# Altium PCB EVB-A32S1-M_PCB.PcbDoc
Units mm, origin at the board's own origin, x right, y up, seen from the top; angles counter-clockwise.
Board outline 134 x 65 mm, 4 copper layers (L1 (Signal), L2 (GND), L3 (PWR), L4 (Signal)), stack 1.614 mm thick; 111 components, 86 nets, 390 pads, 0 vias.
Unrouted connection lines stored in the file: 284.
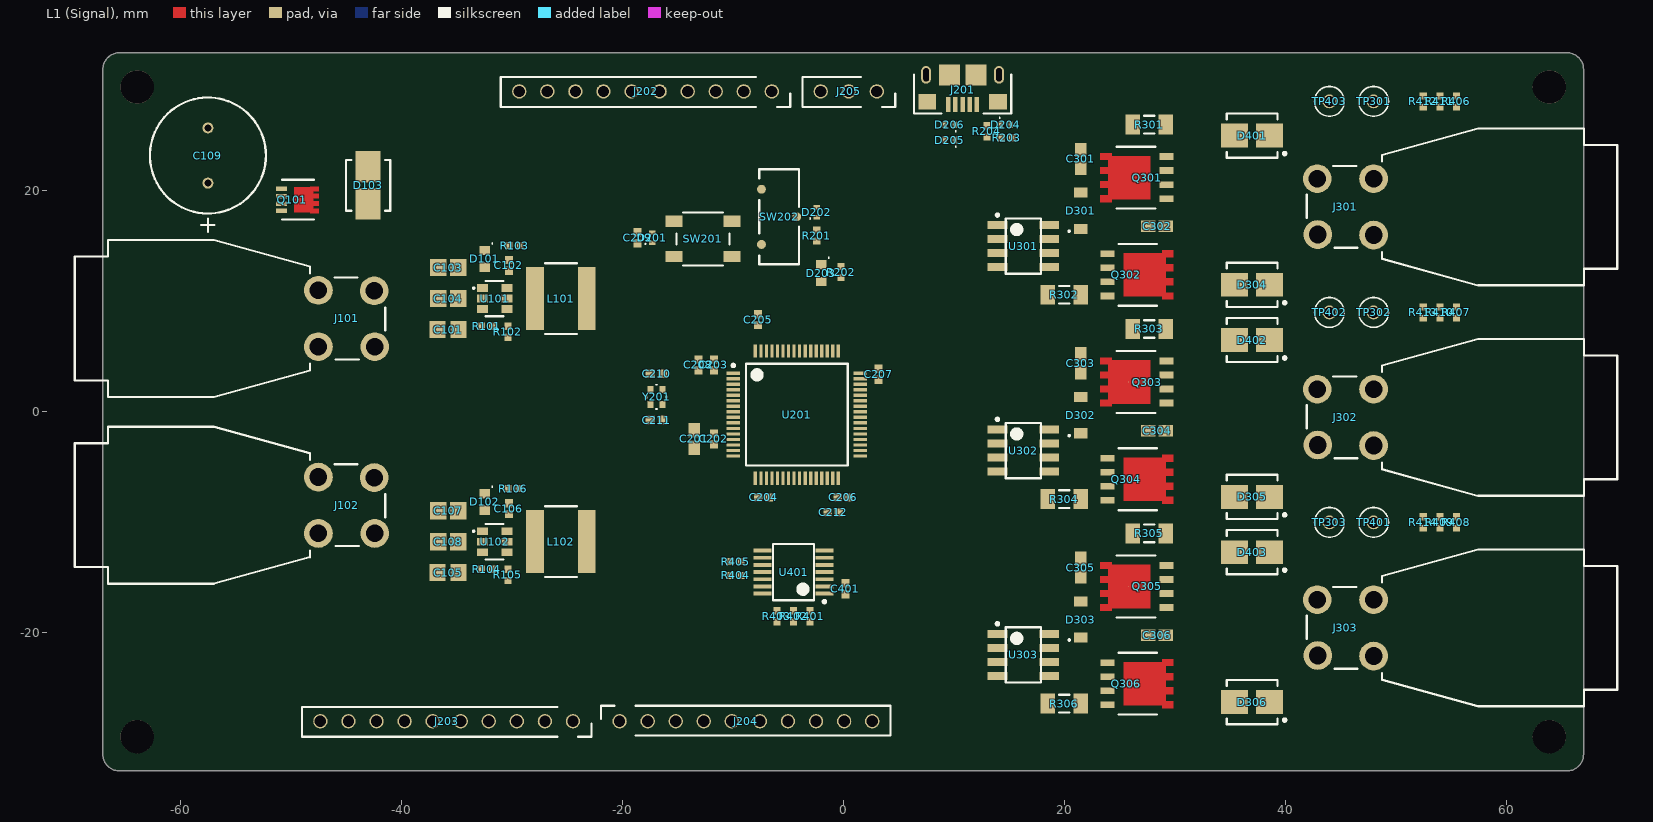
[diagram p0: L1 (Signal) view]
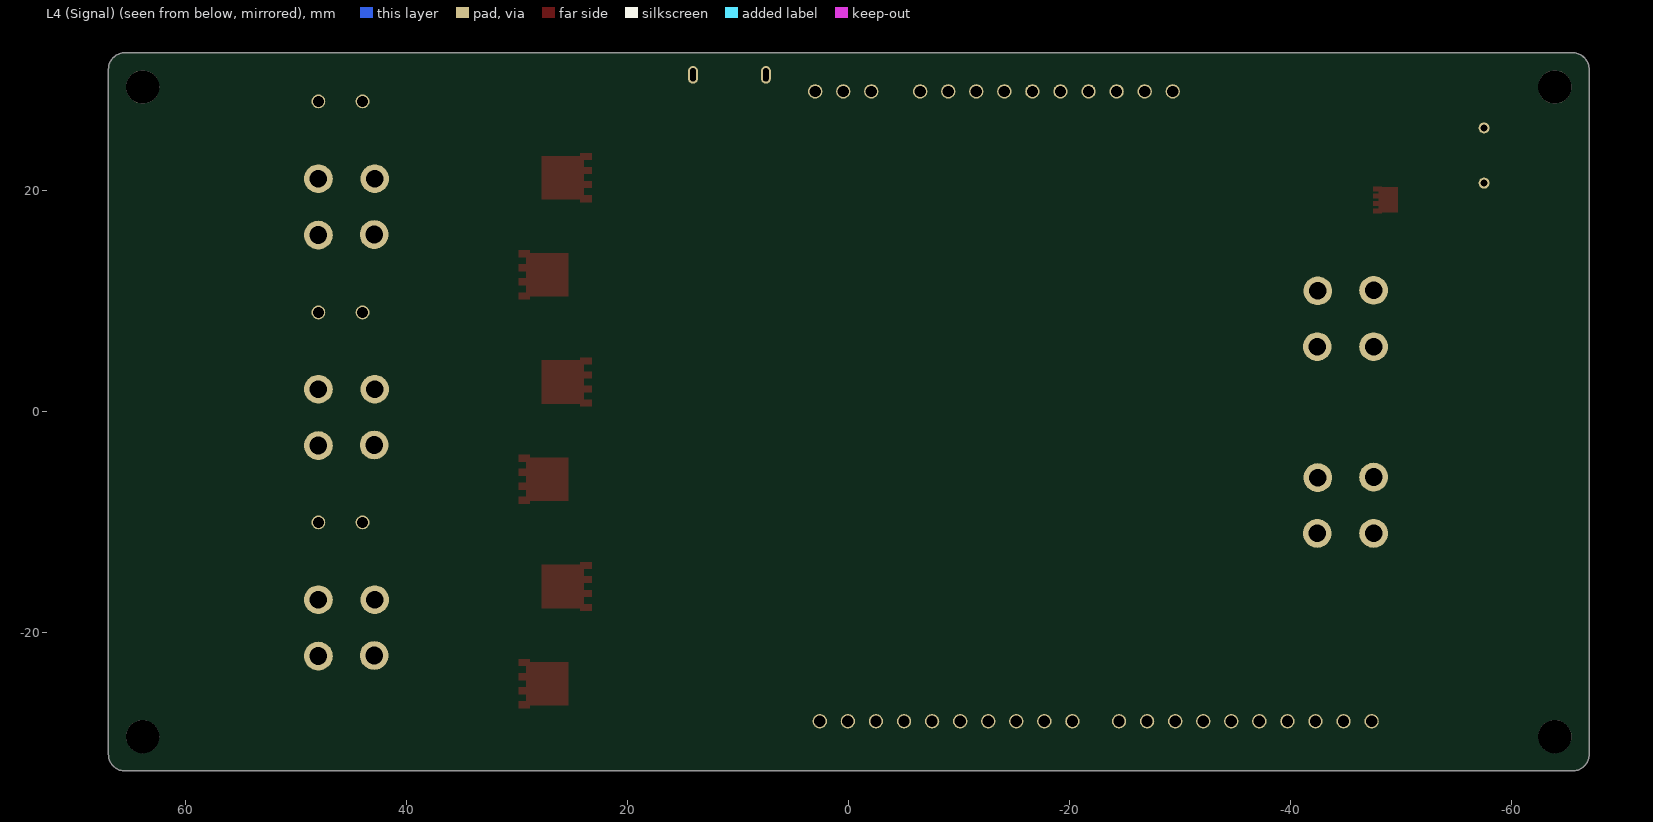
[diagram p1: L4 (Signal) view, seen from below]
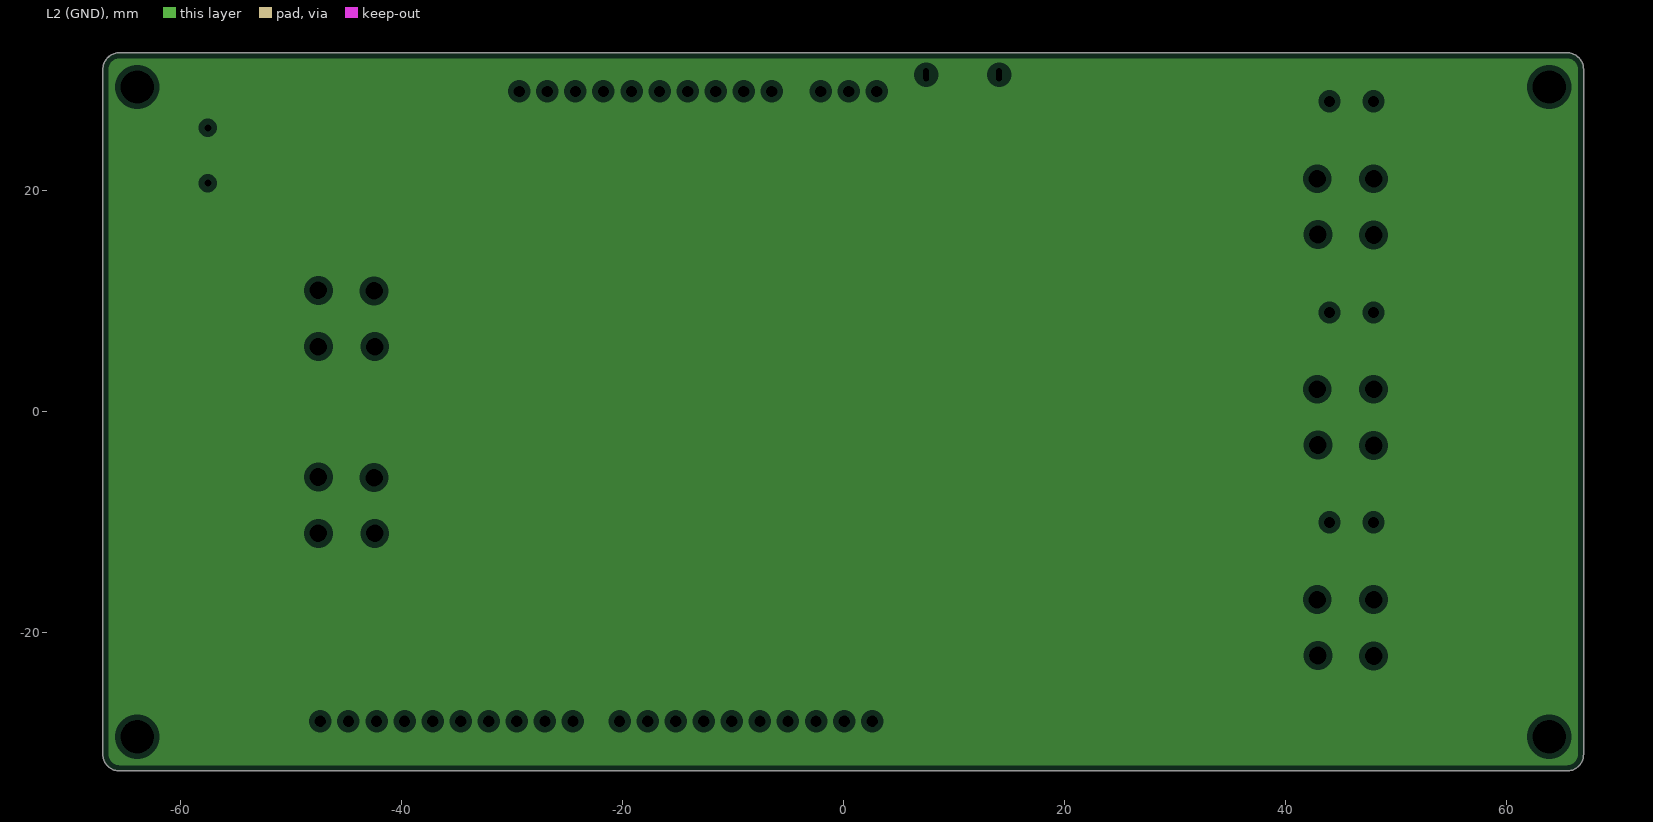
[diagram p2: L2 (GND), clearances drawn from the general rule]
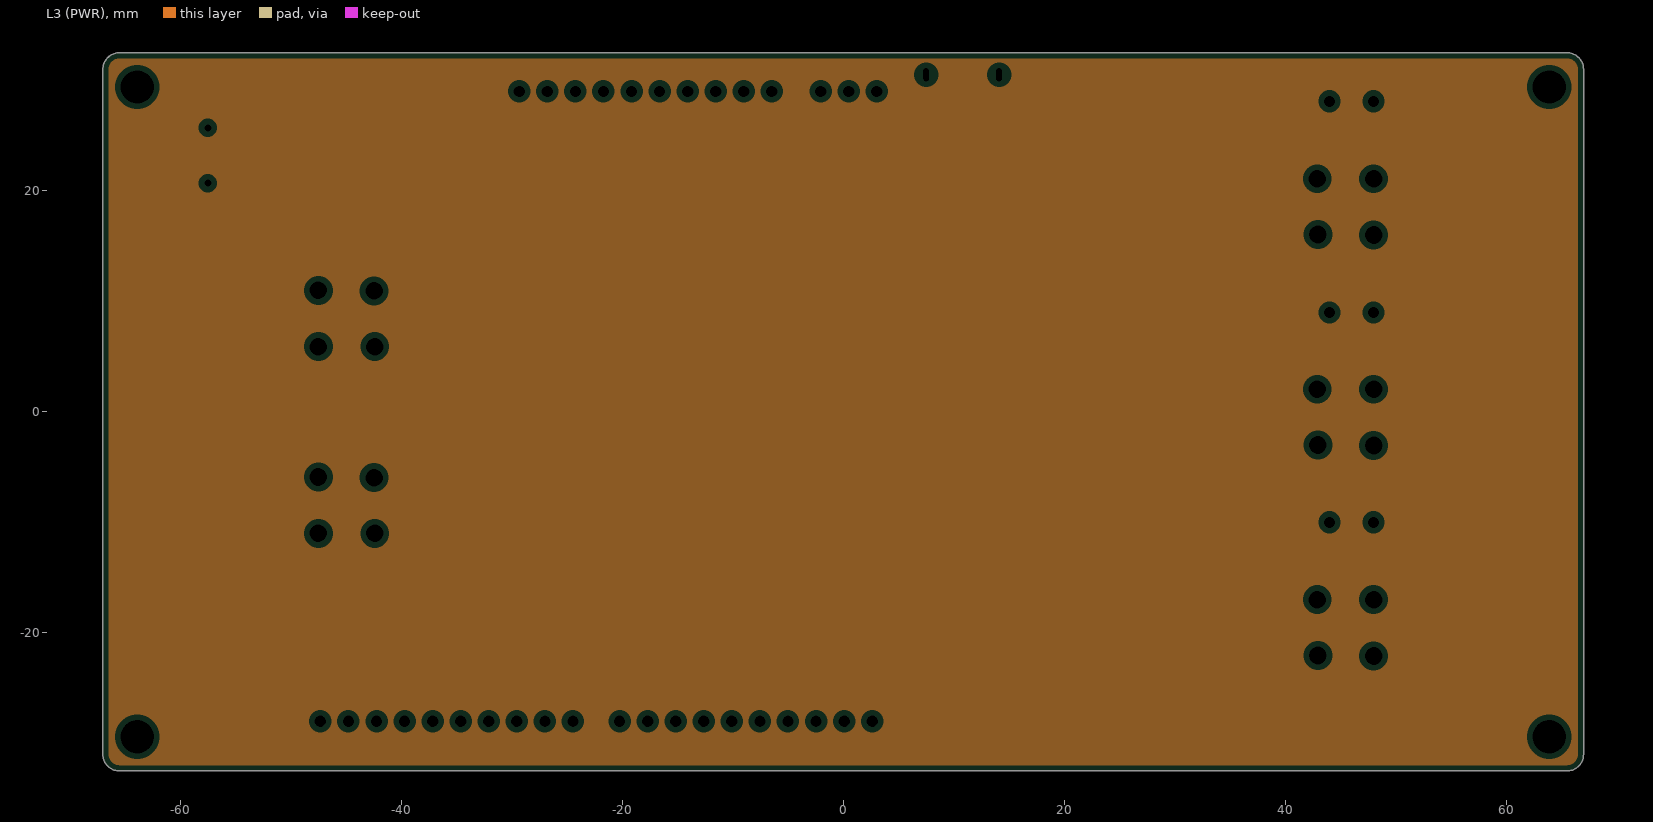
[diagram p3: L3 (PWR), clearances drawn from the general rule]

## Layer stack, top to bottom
Top Solder: solder mask 0.0254, SM-001, Dk 4
L1 (Signal): signal copper 0.07
PP1_3313: prepreg 0.092, PP-017, Dk 4.1
L2 (GND): plane copper 0.03
C_FR4: core 1.23, Core-039, Dk 4.6
L3 (PWR): plane copper 0.03
PP2_3313: prepreg 0.092, PP-017, Dk 4.1
L4 (Signal): signal copper 0.07
Bottom Solder: solder mask 0.0254, SM-001, Dk 4

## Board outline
-67,-31 -67,31 cw(c-65.5,31) -65.5,32.5 65.5,32.5 cw(c65.5,31) 67,31 67,-31 cw(c65.5,-31) 65.5,-32.5 -65.5,-32.5 cw(c-65.5,-31)

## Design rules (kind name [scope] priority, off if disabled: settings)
Clearance ClearanceDiffNets [All] p1: gap=0.26 ignorepadtopadclearanceinfootprint=FALSE except(0.12: Arc-Arc Arc-Track Track-Track; 0.15: SMDPad-SMDPad; 0.2: Arc-Text Track-Text SMDPad-Text THPad-Text Via-Text Fill-Text Poly-Text Region-Text Text-Text Text-Hole; 0.22: Arc-SMDPad Track-SMDPad; 0.35: Arc-THPad Arc-Hole Track-THPad Track-Hole Fill-Hole Poly-Hole Region-Hole; 0.52: THPad-THPad THPad-Via THPad-Hole Via-Via Via-Hole)
DiffPairsRouting DiffUSBRouting [InDifferentialPairClass('DIFF_USB')] p1: maxlimit=0.22 minlimit=0.22 mostfreqgap=0.22 toplayer_minwidth=0.289 toplayer_maxwidth=0.289 toplayer_prefwidth=0.15 bottomlayer_minwidth=0.289 bottomlayer_maxwidth=0.289 bottomlayer_prefwidth=0.15 impedanceprofiledriven=TRUE impedanceprofileid={67380DBA-2925-4AB4-9893-7A768D5C1371} impedanceprofilevalue=90.000000 maxuncoupledlength=12.7
HoleSize [All] p1: absolutevalues=TRUE maxlimit=6.3 minlimit=0.2 maxpercent=80.000 minpercent=20.000
HoleToHoleClearance [All] p1: gap=0.52 allowstackedmicrovias=TRUE
MinimumAnnularRing [All] p1: minimumring=0.2
MinimumSolderMaskSliver [All] p1: minsoldermaskwidth=0.1
PlaneClearance [All] p1: clearance=0.508
PlaneConnect [All] p1: planeconnectstyle=Relief reliefexpansion=0.508 reliefentries=4 reliefconductorwidth=0.254 reliefairgap=0.254
PolygonConnect [All] p1: thpad.connectstyle=Relief thpad.reliefconductorwidth=0.254 thpad.reliefentries=4 thpad.polygonreliefangle="90 Angle" thpad.airgapwidth=0.254 smdpad.connectstyle=Relief smdpad.reliefconductorwidth=0.254 smdpad.reliefentries=4 smdpad.polygonreliefangle="90 Angle" smdpad.airgapwidth=0.254 via.connectstyle=Direct via.reliefconductorwidth=0.254 via.reliefentries=4 via.polygonreliefangle="90 Angle" via.airgapwidth=0.254
RoutingVias [All] p1: holewidth=0.3 width=0.7 viastyle="Through Hole" minholewidth=0.25 minwidth=0.6 maxholewidth=0.3 maxwidth=0.7
SilkToSolderMaskClearance [IsPad] p1: minsilkscreentomaskgap=0.15 clearancetoexposedcopper=TRUE
SolderMaskExpansion [All] p1: expansion=0.127 istentingtop=FALSE
SupplyNets "Schematic Supply Nets_2" [InNet('+VBAT')] p1: voltage=0.000
SupplyNets "Schematic Supply Nets_4" [InNet('GND')] p2: voltage=0.000
SupplyNets "Schematic Supply Nets_3" [InNet('+VCC')] p3: voltage=0.000
SupplyNets "Schematic Supply Nets_1" [InNet('+5V')] p4: voltage=0.000
SupplyNets "Schematic Supply Nets" [InNet('+3V3')] p5: voltage=0.000
UnRoutedNet [All] p1: checkbadconnections=TRUE
Width [All] p1: maxlimit=1 minlimit=0.15 preferedwidth=0.3
22 further rules are at their usual default settings.

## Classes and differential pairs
differential pair class DIFF_USB: USB_D
component class 4_EVB-A32S1-M_Sensing: C401 D401 D402 D403 R401 R402 R403 R404 R405 R406 R407 R408 R409 R410 R411 R412 R413 R414 TP401 TP402 TP403 U401
component class 3_EVB-A32S1-M_Motor: C301 C302 C303 C304 C305 C306 D301 D302 D303 D304 D305 D306 J301 J302 J303 Q301 Q302 Q303 Q304 Q305 Q306 R301 R302 R303 R304 R305 R306 TP301 TP302 TP303 U301 U302 U303
component class 2_EVB-A32S1-M_MCU: C201 C202 C203 C204 C205 C206 C207 C208 C209 C210 C211 C212 D201 D202 D203 D204 D205 D206 J201 J202 J203 J204 J205 R201 R202 R203 R204 SW201 SW202 U201 Y201
component class 1_EVB-A32S1-M_Power: C101 C102 C103 C104 C105 C106 C107 C108 C109 D101 D102 D103 J101 J102 L101 L102 Q101 R101 R102 R103 R104 R105 R106 U101 U102
differential pair USB_D: +USB_D_P -USB_D_N

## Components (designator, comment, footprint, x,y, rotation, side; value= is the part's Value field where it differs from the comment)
C101 "CL21A106KOQNNNE" C_Samsung_CL_0805_A -35.75,7.45 r0 top value=10uF
C102 "CL05B104KP5NNNC" C_Samsung_CL_0402_A -30.25,13.25 r270 top value=100nF
C103 "CC0805MKX5R6BB226" C_Yageo_CC_0805_A -35.75,13.05 r0 top value=22uF
C104 "CC0805MKX5R6BB226" C_Yageo_CC_0805_A -35.75,10.25 r0 top value=22uF
C105 "CL21A106KOQNNNE" C_Samsung_CL_0805_A -35.75,-14.55 r0 top value=10uF
C106 "CL05B104KP5NNNC" C_Samsung_CL_0402_A -30.25,-8.75 r270 top value=100nF
C107 "CC0805MKX5R6BB226" C_Yageo_CC_0805_A -35.75,-8.95 r0 top value=22uF
C108 "CC0805MKX5R6BB226" C_Yageo_CC_0805_A -35.75,-11.75 r0 top value=22uF
C109 "35ZLH470MEFC10X16" C_Rubycon_10x16mm_TH -57.5,23.2 r90 top value=470uF
C201 "CC0603KRX7R7BB105" C_Yageo_CC_0603_A -13.5,-2.45 r270 top value=1uF
C202 "CL05B104KP5NNNC" C_Samsung_CL_0402_A -11.7,-2.45 r270 top value=100nF
C203 "CL05B104KP5NNNC" C_Samsung_CL_0402_A -11.7,4.25 r270 top value=100nF
C204 "CL05B104KP5NNNC" C_Samsung_CL_0402_A -7.2,-7.75 r0 top value=100nF
C205 "CL05B104KP5NNNC" C_Samsung_CL_0402_A -7.7,8.35 r90 top value=100nF
C206 "CL05B104KP5NNNC" C_Samsung_CL_0402_A 0,-7.75 r0 top value=100nF
C207 "CL05B104KP5NNNC" C_Samsung_CL_0402_A 3.2,3.4 r90 top value=100nF
C208 "CL05A475MP5NRNC" C_Samsung_CL_0402_A -13.1,4.25 r270 top value=4.7uF
C209 "CL05B104KP5NNNC" C_Samsung_CL_0402_A -18.6,15.75 r270 top value=100nF
C210 "CC0402JRNPO9BN150" C_Yageo_CC_0402_A -16.9,3.45 r180 top value=15pF
C211 "CC0402JRNPO9BN150" C_Yageo_CC_0402_A -16.9,-0.75 r0 top value=15pF
C212 "CL05A475MP5NRNC" C_Samsung_CL_0402_A -0.9,-9.1 r180 top value=4.7uF
C301 "CC0603KRX7R7BB105" C_Yageo_CC_0603_A 21.5,22.9 r270 top value=1uF
C302 "CC0603KRX7R7BB105" C_Yageo_CC_0603_A 28.4,16.8 r180 top value=1uF
C303 "CC0603KRX7R7BB105" C_Yageo_CC_0603_A 21.5,4.4 r270 top value=1uF
C304 "CC0603KRX7R7BB105" C_Yageo_CC_0603_A 28.4,-1.7 r180 top value=1uF
C305 "CC0603KRX7R7BB105" C_Yageo_CC_0603_A 21.5,-14.1 r270 top value=1uF
C306 "CC0603KRX7R7BB105" C_Yageo_CC_0603_A 28.4,-20.2 r180 top value=1uF
C401 "CL05B104KP5NNNC" C_Samsung_CL_0402_A 0.2,-16 r90 top value=100nF
D101 "LTST-C190GKT" D_LED_Lite-On_Green_0603_A -32.45,13.85 r270 top
D102 "LTST-C190GKT" D_LED_Lite-On_Green_0603_A -32.45,-8.15 r270 top
D103 "SMBJ15CA-13-F" D_TVS_BI_Diodes_SMBJ15CA-13-F_A -43,20.5 r90 top value=280pF
D201 "D5V0F1U2S9-7" D_TVS_Uni_Diodes_SOD-923_B -17.3,15.75 r90 top value=5E-13F
D202 "D5V0F1U2S9-7" D_TVS_Uni_Diodes_SOD-923_B -2.4,18.05 r90 top value=5E-13F
D203 "LTST-C190GKT" D_LED_Lite-On_Green_0603_A -2,12.55 r270 top
D204 "D5V0F1U2S9-7" D_TVS_Uni_Diodes_SOD-923_B 14.7,26 r0 top value=5E-13F
D205 "D5V0F1U2S9-7" D_TVS_Uni_Diodes_SOD-923_B 9.65,24.6 r180 top value=5E-13F
D206 "D5V0F1U2S9-7" D_TVS_Uni_Diodes_SOD-923_B 9.65,26 r180 top value=5E-13F
D301 "B5819W-TP" D_Schottky_MCC_SOD-123 21.5,18.2 r90 top
D302 "B5819W-TP" D_Schottky_MCC_SOD-123 21.5,-0.3 r90 top
D303 "B5819W-TP" D_Schottky_MCC_SOD-123 21.5,-18.8 r90 top
D304 "SMBJ15A-13-F" D_TVS_Uni_Diodes_DO-214AA_B 37,11.5 r180 top value=800pF
D305 "SMBJ15A-13-F" D_TVS_Uni_Diodes_DO-214AA_B 37,-7.7 r180 top value=800pF
D306 "SMBJ15A-13-F" D_TVS_Uni_Diodes_DO-214AA_B 37,-26.27 r180 top value=800pF
D401 "SMBJ15A-13-F" D_TVS_Uni_Diodes_DO-214AA_B 37,25 r180 top value=800pF
D402 "SMBJ15A-13-F" D_TVS_Uni_Diodes_DO-214AA_B 37,6.5 r180 top value=800pF
D403 "SMBJ15A-13-F" D_TVS_Uni_Diodes_DO-214AA_B 37,-12.7 r180 top value=800pF
J101 "CT3151SP-2" J_CalTest_CT3151SP-2 -44.95,8.45 r0 top
J102 "CT3151SP-0" J_CalTest_CT3151SP-0 -44.95,-8.45 r0 top
J201 "10118193-0001LF" J_USB_Micro-B_Amphenol_10118193-0001LF 10.8,30.5 r180 top
J202 "PPPC101LFBN-RC" J_Sullins_01x07_Socket_2.54mm -17.89,29 r180 top
J203 "PPPC101LFBN-RC" J_Sullins_01x07_Socket_2.54mm -35.89,-28 r180 top
J204 "PPPC101LFBN-RC" J_Sullins_01x07_Socket_2.54mm -8.81,-28 r0 top
J205 "PPPC031LFBN-RC" J_Sullins_01x03_Socket_2.54mm 0.5,29 r180 top
J301 "CT3151SP-0" J_CalTest_CT3151SP-0 45.45,18.55 r180 top
J302 "CT3151SP-0" J_CalTest_CT3151SP-0 45.45,-0.5 r180 top
J303 "CT3151SP-0" J_CalTest_CT3151SP-0 45.45,-19.55 r180 top
L101 "1255AY-3R9N=P3" L_Murata_1255AY-XXXX=P3 -25.55,10.25 r0 top value=3.9uH
L102 "1255AY-4R7M=P3" L_Murata_1255AY-XXXX=P3 -25.55,-11.75 r0 top value=4.7uH
Q101 "SI7617DN-T1-GE3" Q_Vishay_PowerPACK-1212-8 -49.4,19.2 r0 top
Q301 "SIR182DP-T1-RE3" Q_Vishay_PowerPACK-SO-8-Single 26.75,21.2 r180 top
Q302 "SIR182DP-T1-RE3" Q_Vishay_PowerPACK-SO-8-Single 26.4,12.4 r0 top
Q303 "SIR182DP-T1-RE3" Q_Vishay_PowerPACK-SO-8-Single 26.75,2.7 r180 top
Q304 "SIR182DP-T1-RE3" Q_Vishay_PowerPACK-SO-8-Single 26.4,-6.1 r0 top
Q305 "SIR182DP-T1-RE3" Q_Vishay_PowerPACK-SO-8-Single 26.75,-15.8 r180 top
Q306 "SIR182DP-T1-RE3" Q_Vishay_PowerPACK-SO-8-Single 26.4,-24.6 r0 top
R101 "RC0402FR-07110KL" R_Yageo_RCL_0402_A -32.25,7.75 r180 top value=110kR
R102 "RC0402FR-0713KL" R_Yageo_RCL_0402_A -30.35,7.25 r90 top value=13kR
R103 "RC0402FR-071KL" R_Yageo_RCL_0402_A -29.75,15.05 r180 top value=1kR
R104 "RC0402FR-07110KL" R_Yageo_RCL_0402_A -32.25,-14.25 r180 top value=110kR
R105 "RC0402FR-0713KL" R_Yageo_RCL_0402_A -30.35,-14.75 r90 top value=13kR
R106 "RC0402FR-071KL" R_Yageo_RCL_0402_A -29.85,-6.95 r180 top value=1kR
R201 "RC0402FR-0710KL" R_Yageo_RCL_0402_A -2.4,15.95 r270 top value=10kR
R202 "RC0402FR-071KL" R_Yageo_RCL_0402_A -0.2,12.65 r90 top value=1kR
R203 "RC0402FR-0733KL" R_Yageo_RCL_0402_A 14.8,24.8 r180 top value=33kR
R204 "RC0402FR-0713KL" R_Yageo_RCL_0402_A 13,25.4 r90 top value=13kR
R301 "RC1206FR-07100RL" R_Yageo_RCL_1206_A 27.7,26 r0 top value=100R
R302 "RC1206FR-07100RL" R_Yageo_RCL_1206_A 20,10.6 r0 top value=100R
R303 "RC1206FR-07100RL" R_Yageo_RCL_1206_A 27.7,7.5 r0 top value=100R
R304 "RC1206FR-07100RL" R_Yageo_RCL_1206_A 20,-7.9 r0 top value=100R
R305 "RC1206FR-07100RL" R_Yageo_RCL_1206_A 27.7,-11 r0 top value=100R
R306 "RC1206FR-07100RL" R_Yageo_RCL_1206_A 20,-26.4 r0 top value=100R
R401 "RC0402FR-0710KL" R_Yageo_RCL_0402_A -3,-18.5 r270 top value=10kR
R402 "RC0402FR-0710KL" R_Yageo_RCL_0402_A -4.5,-18.5 r270 top value=10kR
R403 "RC0402FR-0710KL" R_Yageo_RCL_0402_A -6,-18.5 r270 top value=10kR
R404 "RC0402FR-0710KL" R_Yageo_RCL_0402_A -9.75,-14.8 r0 top value=10kR
R405 "RC0402FR-0710KL" R_Yageo_RCL_0402_A -9.75,-13.55 r0 top value=10kR
R406 "RC0402FR-0733KL" R_Yageo_RCL_0402_A 55.5,28.1 r90 top value=33kR
R407 "RC0402FR-0733KL" R_Yageo_RCL_0402_A 55.5,9 r90 top value=33kR
R408 "RC0402FR-0733KL" R_Yageo_RCL_0402_A 55.5,-10 r90 top value=33kR
R409 "RC0402FR-0710KL" R_Yageo_RCL_0402_A 54,-10 r90 top value=10kR
R410 "RC0402FR-0710KL" R_Yageo_RCL_0402_A 54,9 r90 top value=10kR
R411 "RC0402FR-0710KL" R_Yageo_RCL_0402_A 54,28.1 r90 top value=10kR
R412 "RC0402FR-0733KL" R_Yageo_RCL_0402_A 52.5,28.1 r270 top value=33kR
R413 "RC0402FR-0733KL" R_Yageo_RCL_0402_A 52.5,9 r270 top value=33kR
R414 "RC0402FR-0733KL" R_Yageo_RCL_0402_A 52.5,-10 r270 top value=33kR
SW201 "PTS647SN50SMTR2LFS" SW_Tactitle_SPST_C&K_PTS647SN50SMTR2LFS -12.7,15.65 r180 top
SW202 "JS102011JCQN" SW_Slide_C&K_JS102011JCQN -5.8,17.65 r270 top
TP301 "5001" TP_Keystone_TH 48,28.1 r90 top
TP302 "5001" TP_Keystone_TH 48,9 r90 top
TP303 "5001" TP_Keystone_TH 44,-10 r90 top
TP401 "5001" TP_Keystone_TH 48,-10 r90 top
TP402 "5001" TP_Keystone_TH 44,9 r90 top
TP403 "5001" TP_Keystone_TH 44,28.1 r90 top
U101 "AP63203WU-7" U_Diodes_AP623xx -31.55,10.25 r270 top
U102 "AP63205WU-7" U_Diodes_AP623xx -31.55,-11.75 r270 top
U201 "STM32F401RET6" U_ST_STM32F401xD/xE_B -4.2,-0.25 r0 top
U301 "IR2103STRPBF" U_Infineon_8-SOIC_3.9mm 16.3,15 r0 top
U302 "IR2103STRPBF" U_Infineon_8-SOIC_3.9mm 16.3,-3.5 r0 top
U303 "IR2103STRPBF" U_Infineon_8-SOIC_3.9mm 16.3,-22 r0 top
U401 "LM339APWR" U_TI_14-TSSOP-5.00x4.40mm_0.62mm_B -4.5,-14.5 r180 top
Y201 "ECS-240-12-37B-CKY-TR" Y_Crystal_GND24_ECS_240-12-37B-CKY-TR -16.9,1.35 r270 top

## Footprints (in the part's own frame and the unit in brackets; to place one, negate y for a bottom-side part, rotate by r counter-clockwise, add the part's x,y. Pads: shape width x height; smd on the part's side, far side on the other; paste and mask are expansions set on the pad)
C_Rubycon_10x16mm_TH [mm]
  round 1 hole 0.65: 1(-2.5,0) 2(2.5,0)
  silkscreen extent -6.9,-5.25 5.25,5.25, body extent -5.11,-5.1 5.11,5.1, height 16.46
C_Samsung_CL_0402_A [mm] "Chip Capacitor, 2-Leads, Body 1.00x0.50mm, IPC Low Density"
  rect 0.76x0.72 smd mask+0.05: 1(-0.49,0) 2(0.49,0)
  body extent -0.53,-0.28 0.53,0.28, height 0.55
C_Samsung_CL_0805_A [mm] "Chip Capacitor, 2-Leads, Body 2.00x1.25mm, IPC Low Density"
  rect 1.45x1.55 smd: 1(-0.95,0) 2(0.95,0)
  body extent -1.07,-0.7 1.07,0.7, height 1.4
C_Yageo_CC_0402_A [mm] "Yageo series CC Chip Capacitor, 2-Leads, Body 1.00x0.50mm, IPC Low Density"
  rect 0.86x0.8 smd mask+0.07: 1(-0.55,0) 2(0.55,0)
  body extent -0.53,-0.28 0.53,0.28, height 0.7
C_Yageo_CC_0603_A [mm] "Yageo series CC Chip Capacitor, 2-Leads, Body 1.60x0.80mm, IPC Low Density"
  rect 1.3x1.05 smd mask+0.09: 1(-0.8,0) 2(0.8,0)
  body extent -0.9,-0.5 0.9,0.5, height 1
C_Yageo_CC_0805_A [mm] "Yageo series CC Chip Capacitor, 2-Leads, Body 2.00x1.25mm, IPC Low Density"
  rect 1.5x1.55 smd mask+0.09: 1(-0.9,0) 2(0.9,0)
  body extent -1.1,-0.72 1.1,0.72, height 1.45
D_LED_Lite-On_Green_0603_A [mm] "Chip Diode, 2-Leads, Body 1.60x0.70mm, IPC Low Density"
  rect 0.85x0.95 smd: 1(-0.75,0) 2(0.75,0)
  silkscreen extent -1.44,0.64 -1.34,0.74, body extent -0.8,-0.4 0.8,0.4, height 0.8
D_Schottky_MCC_SOD-123 [mm]
  rect 0.91x1.22 smd: 1(-1.635,0) 2(1.635,0)
  silkscreen extent -1.89,1.01 -1.81,1.09, body extent -1.83,-0.85 1.88,0.85, height 1.21
D_TVS_BI_Diodes_SMBJ15CA-13-F_A [mm] "Molded Diode, 2-Leads, Body 4.31x3.62mm, IPC Low Density"
  rect 2.85x2.25 smd: 1(-1.675,0) 2(1.675,0)
  silkscreen extent -2.3,-2 2.3,2, body extent -2.5,-1.97 2.5,1.97, height 2.44
D_TVS_Uni_Diodes_DO-214AA_B [mm] "Molded Diode, 2-Leads, Body 4.31x3.62mm, IPC Medium Density"
  rect 2.45x2.15 smd: 1(-1.575,0) 2(1.575,0)
  silkscreen extent -3.08,-2 2.3,2, body extent -2.5,-1.97 2.5,1.97, height 2.5
D_TVS_Uni_Diodes_SOD-923_B [mm] "SODFL, 2-Leads, Body 0.60x1.00mm, IPC Medium Density"
  rect 0.4x0.6 smd: 1(-0.45,0) 2(0.45,0)
  silkscreen extent -0.6,0.55 -0.5,0.65, body extent -0.5,-0.33 0.5,0.33, height 0.4
J_CalTest_CT3151SP-0 [mm] "CalTest Banana Jack Connector Standard Banana Solder Black"
  round 2.6 hole 1.6: 1(-2.55,2.55) 2(2.5,2.5) 3(-2.55,-2.55) 4(2.55,-2.55)
  silkscreen extent -24.6,-7.1 3.5,7.1, body extent -24.69,-6.73 3.11,6.73, height 14.35
J_CalTest_CT3151SP-2 [mm] "CalTest Banana Jack Connector Standard Banana Solder Red"
  round 2.6 hole 1.6: 1(-2.55,2.55) 2(2.5,2.5) 3(-2.55,-2.55) 4(2.55,-2.55)
  silkscreen extent -24.6,-7.1 3.5,7.1, body extent -24.69,-6.73 3.11,6.73, height 14.35
J_Sullins_01x03_Socket_2.54mm [mm]
  round 1.3 hole 1.02 mask+0.05: 1(-2.54,0) 2(0,0) 3(2.54,0)
  silkscreen extent -4.21,-1.3 4.19,1.4, body extent -4.06,-1.27 4.06,1.27, height 8.5
J_Sullins_01x07_Socket_2.54mm [mm]
  round 1.3 hole 1.02 mask+0.05: 1(-11.43,0) 2(-8.89,0) 3(-6.35,0) 4(-3.81,0) 5(-1.27,0) 6(1.27,0) 7(3.81,0) 8(6.35,0) 9(8.89,0) 10(11.43,0)
  silkscreen extent -13.1,-1.3 13.1,1.4, body extent -12.95,-1.27 12.95,1.27, height 8.5
J_USB_Micro-B_Amphenol_10118193-0001LF [mm] "USB - micro B USB 2.0 Receptacle Connector 5 Position Surface Mount, Right Angle; Through Hole"
  rect 0.4x1.35 smd mask+0.05: 1(-1.3,2.675) 2(-0.65,2.675) 3(0,2.675) 4(0.65,2.675) 5(1.3,2.675)
  rect 1.6x1.4 smd mask+0.05: 6(-3.2,2.45) 7(3.2,2.45)
  rect 1.9x1.9 smd mask+0.05: 8(1.2,0) 9(-1.2,0)
  oval 0.9x1.6 hole 0.5 slot 1.2 at 90 deg mask+0.05: 10(3.3,0) 11(-3.3,0)
  silkscreen extent -4.4,0 4.4,3.5, body extent -3.93,-2.76 3.93,2.95, height 2.81
L_Murata_1255AY-XXXX=P3 [mm]
  rect 1.6x5.7 smd: 1(-2.35,0) 2(2.35,0)
  silkscreen extent -1.45,-3.2 1.45,3.2, body extent -3,-3 3,3, height 4.51
Q_Vishay_PowerPACK-1212-8 [mm]
  rect 0.99x0.405 smd mask+0.05: 1(-1.435,0.975) 2(-1.435,0.315) 3(-1.435,-0.345) 4(-1.435,-1.005)
  round 0.025 smd mask+0.05: 5(0.5,0.025)
  L1 (Signal) region: 1.175,-1.207 1.935,-1.207 1.935,-0.803 1.418,-0.803 1.418,-0.547 1.935,-0.547 1.935,-0.143 1.418,-0.143 1.418,0.113 1.935,0.113 1.935,0.517 1.418,0.517 1.418,0.773 1.935,0.773 1.935,1.177 1.175,1.177 1.175,1.11 -0.307,1.11 -0.307,-1.125 1.175,-1.125
  silkscreen extent -1.4,-1.8 1.5,1.8, body extent -1.65,-1.65 1.65,1.65, height 1.13
Q_Vishay_PowerPACK-SO-8-Single [mm]
  rect 1.27x0.61 smd: 1(-2.485,1.905) 2(-2.485,0.635) 3(-2.485,-0.635) 4(-2.485,-1.905)
  round 0.025 smd: 5(0.95,0)
  L1 (Signal) region: 2.465,-2.21 3.485,-2.21 3.485,-1.6 2.78,-1.6 2.78,-0.94 3.485,-0.94 3.485,-0.33 2.78,-0.33 2.78,0.33 3.485,0.33 3.485,0.94 2.78,0.94 2.78,1.6 3.485,1.6 3.485,2.21 2.465,2.21 2.465,1.955 -1.03,1.955 -1.03,-1.955 2.465,-1.955
  silkscreen extent -1.5,-2.8 2,2.8, body extent -2.92,-2.65 3.32,2.65, height 1.09
R_Yageo_RCL_0402_A [mm] "Yageo series RC_L Chip Resistor, 2-Leads, Body 1.00x0.50mm, IPC Low Density"
  rect 0.65x0.65 smd mask+0.05: 1(-0.5,0) 2(0.5,0)
  body extent -0.53,-0.28 0.53,0.28, height 0.4
R_Yageo_RCL_1206_A [mm] "Yageo series RC_L Chip Resistor, 2-Leads, Body 3.10x1.60mm, IPC Low Density"
  rect 1.3x1.8 smd: 1(-1.5,0) 2(1.5,0)
  silkscreen extent -0.45,-0.8 0.45,0.8, body extent -1.6,-0.85 1.6,0.85, height 0.65
SW_Slide_C&K_JS102011JCQN [mm] "Slide Switch SPDT Surface Mount"
  round 0.8 smd mask+0.05: 1(-2.5,-1.6) 2(0,1.6) 3(2.5,-1.6)
  silkscreen extent -4.3,-1.8 4.3,1.8, body extent -4.25,-2 4.25,2, height 5.4
SW_Tactitle_SPST_C&K_PTS647SN50SMTR2LFS [mm] "Tactitle switch SPST-NO 4.5mm x 4.5mm"
  rect 1.55x1 smd mask+0.05: 1(-2.625,1.6) 2(2.625,1.6) 3(-2.625,-1.6) 4(2.625,-1.6)
  silkscreen extent -2.4,-2.4 2.4,2.4, body extent -3.25,-2.25 3.25,2.25, height 5
TP_Keystone_TH [mm]
  round 1.25 hole 1: 1(0,0)
  silkscreen extent -1.35,-1.35 1.35,1.35, body extent -1.27,-1.26 1.27,1.26, height 4.57
U_Diodes_AP623xx [mm]
  rect 0.7x1 smd mask+0.05: 1(-0.95,-1.1) 2(0,-1.1) 3(0.95,-1.1) 4(0.95,1.1) 5(0,1.1) 6(-0.95,1.1)
  silkscreen extent -1.6,-1.94 1.6,0.8, body extent -1.45,-1.45 1.45,1.45, height 0.91
U_Infineon_8-SOIC_3.9mm [mm] "SOIC, 8-Leads, Body 4.90x3.90mm, Pitch 1.27mm, IPC Medium Density"
  rect 1.78x0.72 smd: 1(-2.34,1.905) 2(-2.34,0.635) 3(-2.34,-0.635) 4(-2.34,-1.905) 5(2.34,-1.905) 6(2.34,-0.635) 7(2.34,0.635) 8(2.34,1.905)
  silkscreen extent -2.46,-2.5 1.6,2.94, body extent -3,-2.5 3,2.5, height 1.75
U_ST_STM32F401xD/xE_B [mm] "TSQFP, 64-Leads, Body 10.00x10.00mm, Pitch 0.50mm, IPC Medium Density"
  rect 1.2x0.3 smd mask+0.05: 1(-5.75,3.75) 2(-5.75,3.25) 3(-5.75,2.75) 4(-5.75,2.25) 5(-5.75,1.75) 6(-5.75,1.25) 7(-5.75,0.75) 8(-5.75,0.25) 9(-5.75,-0.25) 10(-5.75,-0.75) 11(-5.75,-1.25) 12(-5.75,-1.75) 13(-5.75,-2.25) 14(-5.75,-2.75) 15(-5.75,-3.25) 16(-5.75,-3.75) 33(5.75,-3.75) 34(5.75,-3.25) 35(5.75,-2.75) 36(5.75,-2.25) 37(5.75,-1.75) 38(5.75,-1.25) 39(5.75,-0.75) 40(5.75,-0.25) 41(5.75,0.25) 42(5.75,0.75) 43(5.75,1.25) 44(5.75,1.75) 45(5.75,2.25) 46(5.75,2.75) 47(5.75,3.25) 48(5.75,3.75)
  rect 0.3x1.2 smd mask+0.05: 17(-3.75,-5.75) 18(-3.25,-5.75) 19(-2.75,-5.75) 20(-2.25,-5.75) 21(-1.75,-5.75) 22(-1.25,-5.75) 23(-0.75,-5.75) 24(-0.25,-5.75) 25(0.25,-5.75) 26(0.75,-5.75) 27(1.25,-5.75) 28(1.75,-5.75) 29(2.25,-5.75) 30(2.75,-5.75) 31(3.25,-5.75) 32(3.75,-5.75) 49(3.75,5.75) 50(3.25,5.75) 51(2.75,5.75) 52(2.25,5.75) 53(1.75,5.75) 54(1.25,5.75) 55(0.75,5.75) 56(0.25,5.75) 57(-0.25,5.75) 58(-0.75,5.75) 59(-1.25,5.75) 60(-1.75,5.75) 61(-2.25,5.75) 62(-2.75,5.75) 63(-3.25,5.75) 64(-3.75,5.75)
  silkscreen extent -5.87,-4.6 4.6,4.6, body extent -6,-6 6,6, height 1.6
U_TI_14-TSSOP-5.00x4.40mm_0.62mm_B [mm] "TSOP, 14-Leads, Body 5.00x4.40mm, Pitch 0.65mm, IPC Medium Density"
  rect 1.6x0.35 smd: 1(-2.8,1.95) 2(-2.8,1.3) 3(-2.8,0.65) 4(-2.8,0) 5(-2.8,-0.65) 6(-2.8,-1.3) 7(-2.8,-1.95) 8(2.8,-1.95) 9(2.8,-1.3) 10(2.8,-0.65) 11(2.8,0) 12(2.8,0.65) 13(2.8,1.3) 14(2.8,1.95)
  silkscreen extent -2.93,-2.55 1.85,2.8, body extent -3.2,-2.55 3.2,2.55, height 1.2
Y_Crystal_GND24_ECS_240-12-37B-CKY-TR [mm]
  rect 0.65x0.55 smd mask+0.05: 1(-0.675,-0.525) 2(0.675,-0.525) 3(0.675,0.525) 4(-0.675,0.525)
  silkscreen extent -1.1,-0.9 1.1,0.9, body extent -1,-0.8 1,0.8, height 0.51

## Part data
C101 C105: library part CMP-001-00022-4, "Multilayer Ceramic Capacitor, 10 uF, 16 V, ± 10%, X5R, 0805 [2012 Metric]", Case Code (Imperial)=0805, Case Code (Metric)=2012, Dielectric=X7R, Max Operating Temperature=85°C, Min Operating Temperature=-55°C, Package Quantity=1, Tolerance=10%, Voltage=16V
C102 C106 C202 C203 C204 C205 C206 C207 C209 C401: library part CMP-001-00023-3, "Multilayer Ceramic Capacitor, 0.1 uF, 10 V, ± 10%, X7R, 0402 [1005 Metric]", Case Code (Imperial)=0402, Case Code (Metric)=1005, Dielectric=X7R, Max Operating Temperature=125°C, Min Operating Temperature=-55°C, Package Quantity=1, Tolerance=10%, Voltage Rating=10V
C103 C104 C107 C108: library part CMP-001-00014-8, "Multilayer Ceramic Capacitor, 22 uF, 10 V, ± 20%, X5R, 0805 [2012 Metric]", Case Code (Imperial)=0805, Case Code (Metric)=2012, Dielectric=X5R, Max Operating Temperature=85°C, Min Operating Temperature=-55°C, Tolerance=20%, Voltage Rating=10V
C109: library part CMP-001-00025-4, "Cap Aluminum 470uF 35V 20% (10 X 16mm) Radial 5mm 1760mA 10000h 105 C Bulk", Case/Package=Radial, Dielectric Material=Aluminium, Leakage Current=3uA, Max Operating Temperature=105°C, Min Operating Temperature=-40°C, Ripple Current=1.76A, Tolerance=20%, Voltage=35V
C201 C301 C302 C303 C304 C305 C306: library part CMP-001-00019-4, "Multilayer Ceramic Capacitor, 1 uF, 16 V, ± 10%, X7R, 0603 [1608 Metric]", Case Code (Imperial)=0603, Case Code (Metric)=1608, Dielectric=X7R, Max Operating Temperature=125°C, Min Operating Temperature=-55°C, Package Quantity=1, Tolerance=10%, Voltage=16V
C208 C212: library part CMP-001-00024-3, "Multilayer Ceramic Capacitor, 4.7 uF, 10 V, ± 20%, X5R, 0402 [1005 Metric]", Case Code (Imperial)=0402, Case Code (Metric)=1005, Dielectric=X5R, Max Operating Temperature=85°C, Min Operating Temperature=-55°C, Tolerance=20%, Voltage Rating=10V
C210 C211: library part CMP-001-00017-13, "Multilayer Ceramic Capacitor, 15 pF, 10 V, ± 5%, X7R, 0402 [1005 Metric]", Case Code (Imperial)=0402, Case Code (Metric)=1005, Dielectric=C0G, Dielectric Material=Ceramic, Insulation Resistance=100GR, Max Operating Temperature=125°C, Min Operating Temperature=-55°C, Package Quantity=1, Temperature Coefficient=30ppm/°C, Tolerance=5%, Voltage=50V
D101 D102 D203: library part CMP-007-00001-3, "LED Uni-Color Green 565nm 2-Pin Chip LED T/R", Case Code (Imperial)=0603, Case Code (Metric)=1608, Color=Green, Forward Current=30mA, Forward Voltage=2.1V, Lens Color=Colorless, Max Operating Temperature=85°C, Min Operating Temperature=-55°C, Package Quantity=1, Power Dissipation=100mW, Reverse Voltage=5V, Test Current=10mA, Voltage=2V
D103: library part CMP-004-00000-11, "Tvs Diode, Bidir, 15V, 600W, Do-214Aa Rohs Compliant: Yes", Breakdown Voltage=19.2V, Case/Package=SMB, Clamping Voltage=24.4V, Leakage Current=5uA, Max Operating Temperature=150°C, Max Output current=24A, Max Power Dissipation=600W, Min Breakdown Voltage=16.7V, Min Operating Temperature=-55°C, Package Quantity=3000, Power Line Protection=No, Reverse Standoff Voltage=15V, Test Current=1mA
D201 D202 D204 D205 D206: library part CMP-004-00003-4, "Diode TVS Dual Uni-Dir 5.5V 250000W 2-Pin SOD-923 T/R", Breakdown Voltage=6V, Capacitance="0.5pF @ 1MHz", Case/Package=SOD-923-2, Clamping Voltage=10V, Max Operating Temperature=150°C, Max Power Dissipation=250mW, Max Reverse Leakage Current=100nA, Max Surge Current=1.5A, Min Operating Temperature=-65°C, Package Quantity=10000, Peak Pulse Power=250kW, Power Line Protection=Yes, Reverse Standoff Voltage=5.5V
D301 D302 D303: library part CMP-000001-2, "Rectifier Diode, Schottky, 1 Phase, 1 Element, 1A, 40V V(RRM), Silicon", Average Rectified Current=1A, Forward Voltage=550mV, Max Forward Surge Current (Ifsm)=10A, Max Operating Temperature=125°C, Max Power Dissipation=250mW, Max Repetitive Reverse Voltage (Vrrm)=40V, Max Reverse Current=1mA, Max Reverse Voltage (DC)=20V, Min Operating Temperature=-65°C, Package Quantity=3000
D304 D305 D306 D401 D402 D403: library part CMP-004-00005-2, "TVS Diode Single Uni-Dir 15V 600W 2-Pin SMB T/R / TVS DIODE 15VWM 24.4VC SMB", Breakdown Voltage=19.2V, Case/Package=SMB, Clamping Voltage=24.4V, Forward Voltage=5V, Leakage Current=5uA, Max Operating Temperature=150°C, Max Output current=24A, Max Power Dissipation=600W, Min Breakdown Voltage=16.7V, Min Operating Temperature=-55°C, Package Quantity=3000, Power Line Protection=No, Reverse Standoff Voltage=15V, Test Current=1mA
J101: library part CMP-002-00001-13, "Conn 4mm Safety Banana Jack F 1 POS Solder RA Thru-Hole 1 Port Bag", Color=Red, Max Operating Temperature=80°C, Min Operating Temperature=-20°C
J102 J301 J302 J303: library part CMP-002-00000-16, "Conn 4mm Safety Banana Jack F 1 POS Solder RA Thru-Hole 1 Port Bag", Color=Black, Max Operating Temperature=80°C, Min Operating Temperature=-20°C
J201: library part CMP-002-00002-10, "Usb Connector, 5 Contact(S), Female, Right Angle, Surface Mount Terminal, Locking, Receptacle", Color=Black, Current Rating=1.8A, Flammability Rating="UL94 V-0", Insulation Resistance=1GR, Max Operating Temperature=85°C, Max Voltage Rating (AC)=100V, Min Operating Temperature=-55°C, Package Quantity=1200
J202 J203 J204: library part CMP-002-00003-6, "10 Position Total Single Row 2.54 mm Pitch Straight Female Header", Color=Black, Current Rating=3A, Max Operating Temperature=105°C, Min Operating Temperature=-40°C, Package Quantity=1000, Voltage Rating=250V
J205: library part CMP-002-00004-6, "3 Position Total Single Row 2.54 mm Pitch Straight Female Header", Flammability Rating="UL94 V-0", Insulation Color=Black, Max Operating Temperature=105°C, Min Operating Temperature=-40°C, Voltage Rating=250V
L101: library part CMP-006-00002-7, "Inductor Power Shielded Wirewound 3.9uH 30% 100KHz Ferrite 4.2A 0.0264Ohm DCR 2424 T/R", Case/Package=Nonstandard, Current Rating=4.2A, DC Resistance (DCR)=26.4mR, Max Operating Temperature=85°C, Min Operating Temperature=-40°C, Saturation Current=4.7A, Test Frequency=100kHz, Tolerance=30%
L102: library part CMP-006-00001-10, "Inductor Power Shielded Wirewound 4.7uH 20% 100KHz Ferrite 4A 0.0276Ohm DCR 2424 T/R", Case/Package=Nonstandard, Current Rating=4.5A, DC Resistance (DCR)=27.6mR, Inductance Tolerance=20%, Max DC Current=4A, Max Operating Temperature=85°C, Min Operating Temperature=-40°C, Test Frequency=100kHz
Q101: library part CMP-00000-12, "P CHANNEL MOSFET, -30V, 35A; Transistor; Transistor Polarity: P Channel; Continuous Drain Current Id: -35A; Source", Continuous Drain Current (ID)=-35A, Drain to Source Breakdown Voltage=-30V, Drain to Source Resistance=12.3mR, Gate to Source Voltage (Vgs)=25V, Input Capacitance=1.8nF, Max Operating Temperature=150°C, Max Power Dissipation=52W, Min Operating Temperature=-55°C, Package Quantity=3000, Power Dissipation=3.7W, Threshold Voltage=-2.5V
Q301 Q302 Q303 Q304 Q305 Q306: library part CMP-013-00000-6, "TrenchFET Gen IV Power MOSFET N-Channel Single 60V VDS ±20V VGS 60A ID 8-Pin PowerPAK SOIC T/R", Continuous Drain Current (ID)=60A, Drain to Source Voltage (Vdss)=60V, Input Capacitance=3.25nF, Max Operating Temperature=150°C, Max Power Dissipation=69.4W, Min Operating Temperature=-55°C
R101 R104: library part CMP-009-00000-11, "SMD Chip Resistor, 110 kOhm, ± 1%, 63 mW, 0402 [1005 Metric], Thick Film, General Purpose", Case Code (Imperial)=0402, Case Code (Metric)=1005, Max Operating Temperature=155°C, Max Power Dissipation=63mW, Min Operating Temperature=-55°C, Resistance Tolerance=1%, Resistor Type="Thick Film", Temperature Coefficient=100ppm/°C, Voltage Rating=50V
R102 R105 R204: library part CMP-009-00001-11, "SMD Chip Resistor, 13 kOhm, ± 1%, 63 mW, 0402 [1005 Metric], Thick Film, General Purpose", Case Code (Imperial)=0402, Case Code (Metric)=1005, Max Operating Temperature=155°C, Max Power Dissipation=63mW, Min Operating Temperature=-55°C, Package Quantity=10000, Power Rating=62.5mW, Temperature Coefficient=100ppm/°C, Tolerance=1%, Voltage Rating=50V
R103 R106 R202: library part CMP-009-00002-11, "SMD Chip Resistor, 1 kOhm, ± 1%, 62.5 mW, 0402 [1005 Metric], Thick Film, General Purpose", Case Code (Imperial)=0402, Case Code (Metric)=1005, Max Operating Temperature=155°C, Max Power Dissipation=63mW, Min Operating Temperature=-55°C, Power Rating=62.5mW, Resistance Tolerance=1%, Resistor Type="Thick Film", Temperature Coefficient=100ppm/°C, Voltage Rating=50V
R201 R401 R402 R403 R404 R405 R409 R410 R411: library part CMP-009-00003-11, "SMD Chip Resistor, 10 kOhm, ± 1%, 62.5 mW, 0402 [1005 Metric], Thick Film, General Purpose", Case Code (Imperial)=0402, Case Code (Metric)=1005, Max Operating Temperature=155°C, Max Power Dissipation=63mW, Min Operating Temperature=-55°C, Power Rating=62.5mW, Resistance Tolerance=1%, Resistor Type="Thick Film", Temperature Coefficient=100ppm/°C, Voltage Rating=50V
R203 R406 R407 R408 R412 R413 R414: library part CMP-009-00005-12, "SMD Chip Resistor, 33 kOhm, ± 1%, 63 mW, 0402 [1005 Metric], Thick Film, General Purpose", Case Code (Imperial)=0402, Case Code (Metric)=1005, Max Operating Temperature=155°C, Max Power Dissipation=63mW, Min Operating Temperature=-55°C, Package Quantity=1, Resistance Tolerance=1%, Resistor Type="Thick Film", Temperature Coefficient=100ppm/°C, Voltage Rating=50V
R301 R302 R303 R304 R305 R306: library part CMP-009-00004-12, "SMD Chip Resistor, 100 Ohm, ± 1%, 250 mW, 1206 [3216 Metric], Thick Film, General Purpose", Case Code (Imperial)=1206, Case Code (Metric)=3216, Max Operating Temperature=155°C, Max Power Dissipation=250mW, Min Operating Temperature=-55°C, Package Quantity=5000, Resistance Tolerance=1%, Resistor Type="Thick Film", Temperature Coefficient=100ppm/°C, Voltage Rating=200V
SW201: library part CMP-011-00000-13, "Switch Tactile N.O. SPST Round Button Gull Wing 0.05A 12VDC 100000Cycles 0.98N SMD T/R", Max Operating Temperature=70°C, Min Operating Temperature=-20°C, Operating Force=100gf, Ratings=IP40
SW202: library part CMP-011-00001-10, "JS Series Sub-Miniature Slide Switch SPDT On-On Top Slide 0.3A 6VDC J-Lead Surface Mount T/R", Max Operating Temperature=85°C, Min Operating Temperature=-40°C, Voltage Rating (DC)=6V
TP301 TP302 TP303 TP401 TP402 TP403: library part CMP-000000-4, "TEST POINT, PCB, THROUGH HOLE; Product R; Range: -; Connector Colour: Black; Mounting: Through Hole", Color=Black, Package Quantity=100
U101: library part CMP-019-00004-16, "AP63203 Series 3.3 V 2 A SMT Fixed Low IQ Synchronous Buck - TSOT-26", Max Operating Temperature=85°C, Max Supply Voltage=32V, Min Operating Temperature=-40°C, Min Supply Voltage=3.8V, Nominal Supply Current=22uA, Output Current=2A, Output Voltage=3.3V, Switching Frequency=1.1MHz
U102: library part CMP-019-00003-16, "AP63205 Series 32 V 2 A 1.1 MHz Synchronous Buck Converter -TSOT-26", Max Operating Temperature=85°C, Max Supply Voltage=32V, Min Operating Temperature=-40°C, Min Supply Voltage=3.8V, Nominal Supply Current=22uA, Output Current=2A, Output Voltage=5V, Switching Frequency=1.1MHz
U201: library part CMP-020-00000-10, "MCU 32-bit STM32 ARM Cortex M4 RISC 512KB Flash 1.8V/2.5V/3.3V 64-Pin LQFP Tray", Case/Package=LQFP, Clock Frequency=84MHz, Max Operating Temperature=85°C, Max Power Dissipation=313mW, Max Supply Voltage=3.6V, Min Operating Temperature=-40°C, Min Supply Voltage=1.7V, Nominal Supply Current=1.8uA, Operating Supply Voltage=3.3V, Package Quantity=960
U301 U302 U303: library part CMP-024-00000-5, "600 V half-bridge gate driver IC with shoot through protection, SOIC 8N, RoHS", Case/Package=SOIC, Max Operating Temperature=150°C, Max Output current=360mA, Max Supply Voltage=20V, Min Operating Temperature=-40°C
U401: library part CMP-016-00000-7, "Precision quad differential comparator, commercial grade 14-TSSOP 0 to 70", Case/Package=TSSOP, Input Bias Current=250nA, Input Offset Voltage (Vos)=3mV, Max Dual Supply Voltage=15V, Max Operating Temperature=70°C, Max Supply Current=500uA, Max Supply Voltage=30V, Min Dual Supply Voltage=1V, Min Operating Temperature=0°C, Min Supply Voltage=2V, Output Current=20mA, Output Current per Channel=6mA, Package Quantity=2000, Quiescent Current=2.5mA, Supply Current=2mA, Voltage Gain=106.02dB
Y201: library part CMP-003-00000-8, "Crystal 24MHz ±10ppm (Tol) ±10ppm (Stability) 12pF FUND 50Ohm 4-Pin Mini-CSMD T/R", Case/Package="4-SMD, No Lead", Frequency=24MHz, Load Capacitance=12pF

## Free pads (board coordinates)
  round 3 hole 3 unplated: MH1(-63.9,29.4) MH2(-63.9,-29.4) MH3(63.9,29.4) MH4(63.9,-29.4)

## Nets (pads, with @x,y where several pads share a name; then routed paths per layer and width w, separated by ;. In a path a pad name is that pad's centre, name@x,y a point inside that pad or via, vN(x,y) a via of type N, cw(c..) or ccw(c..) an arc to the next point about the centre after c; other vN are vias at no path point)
3V3_BUCK_BST: C102.2 U101.6
3V3_BUCK_EN: R101.1 R102.2 U101.2
3V3_BUCK_SW: C102.1 L101.1 U101.5
3V3_LED_K: D101.1 R103.2
4IN+: R404.2 U401.11
4IN-: R405.2 U401.10
5V_BUCK_BST: C106.2 U102.6
5V_BUCK_EN: R104.1 R105.2 U102.2
5V_BUCK_SW: C106.1 L102.1 U102.5
5V_LED_K: D102.1 R106.2
+3V3: C103.2 C104.2 C201.2 C202.2 C203.2 C204.2 C205.2 C206.2 C207.2 C208.2 D101.2 J202.2 L101.2 SW202.3 U101.1 U201.1 U201.13 U201.19 U201.32 U201.48 U201.64
+5V: C107.2 C108.2 C401.2 D102.2 J202.1 L102.2 R401.2 R402.2 R403.2 U102.1 U401.3
+VBAT: D103.1 J101.1 J101.2 J101.3 J101.4 Q101.5
+VCC: C101.2 C105.2 C109.1 C301.2 C303.2 C305.2 D301.2 D302.2 D303.2 Q101.1 Q101.2 Q101.3 Q301.5 Q303.5 Q305.5 R101.2 R104.2 U101.3 U102.3 U301.1 U302.1 U303.1
BEMF_A: R406.2 R411.2 R412.1 U401.7
BEMF_B: R407.2 R410.2 R413.1 U401.5
BEMF_C: R408.2 R409.2 R414.1 U401.9
BOOT0: R201.2 U201.60
COM: D401.1 D402.1 D403.1 R406.1 R407.1 R408.1 TP401.1 TP402.1 TP403.1 U401.4 U401.6 U401.8
GHO_A: Q301.4 R301.2
GHO_B: Q303.4 R303.2
GHO_C: Q305.4 R305.2
GLO_A: Q302.4 R302.2
GLO_B: Q304.4 R304.2
GLO_C: Q306.4 R306.2
GND: C101.1 C103.1 C104.1 C105.1 C107.1 C108.1 C109.2 C201.1 C202.1 C203.1 C204.1 C205.1 C206.1 C207.1 C208.1 C209.1 C210.1 C211.1 C212.1 C301.1 C303.1 C305.1 C401.1 D103.2 D201.2 D202.2 D204.2 D205.2 D206.2 D304.2 D305.2 D306.2 D401.2 D402.2 D403.2 J102.1 J102.2 J102.3 J102.4 J201.5 J202.3 J202.4 Q101.4 Q302.1 Q302.2 Q302.3 Q304.1 Q304.2 Q304.3 Q306.1 Q306.2 Q306.3 R102.1 R103.1 R105.1 R106.1 R202.1 R203.1 R404.1 R405.1 R409.1 R410.1 R411.1 SW201.3 SW201.4 SW202.1 U101.4 U102.4 U201.12 U201.18 U201.31 U201.47 U201.63 U301.4 U302.4 U303.4 U401.12 Y201.2 Y201.4
HIN_A: U201.43 U301.2
HIN_B: U201.42 U302.2
HIN_C: U201.41 U303.2
HO_A: R301.1 U301.7
HO_B: R303.1 U302.7
HO_C: R305.1 U303.7
LIN_A: U201.36 U301.3
LIN_B: U201.35 U302.3
LIN_C: U201.34 U303.3
LO_A: R302.1 U301.5
LO_B: R304.1 U302.5
LO_C: R306.1 U303.5
NRST: C209.2 D201.1 SW201.1 SW201.2 U201.7
OSC_IN: C210.2 U201.5 Y201.1
OSC_OUT: C211.2 U201.6 Y201.3
PA0: J204.1 U201.14
PA1: J204.2 U201.15
PA2: J204.3 U201.16
PA3: J204.4 U201.17
PA4: J204.5 U201.20
PA5: J204.6 U201.21
PA6: J204.7 U201.22
PA7: J204.8 U201.23
PB4: J202.5 U201.56
PB5: J202.6 U201.57
PB6: J202.7 U201.58
PB7: J202.8 U201.59
PB8: J202.9 U201.61
PB9: J202.10 U201.62
PC0: J203.1 U201.8
PC1: J203.2 U201.9
PC2: J203.3 U201.10
PC3: J203.4 U201.11
PC4: J203.5 U201.24
PC5: J203.6 U201.25
PC10: J203.7 U201.51
PC13: J203.8 U201.2
PC14: J203.9 U201.3
PC15: J203.10 U201.4
PD2: J204.10 U201.54
PHASE_A: C302.1 D304.1 J301.1 J301.2 J301.3 J301.4 Q301.1 Q301.2 Q301.3 Q302.5 R412.2 TP301.1 U301.6
PHASE_B: C304.1 D305.1 J302.1 J302.2 J302.3 J302.4 Q303.1 Q303.2 Q303.3 Q304.5 R413.2 TP302.1 U302.6
PHASE_C: C306.1 D306.1 J303.1 J303.2 J303.3 J303.4 Q305.1 Q305.2 Q305.3 Q306.5 R414.2 TP303.1 U303.6
PROG_LED: D203.2 U201.53
PROG_LED_K: D203.1 R202.2
SENSE_A: R401.1 U201.28 U401.1
SENSE_B: R402.1 U201.29 U401.2
SENSE_C: R403.1 U201.27 U401.14
SW_BOOT0: D202.1 R201.1 SW202.2
SW_CLK: J205.2 U201.49
SW_IO: J205.1 U201.46
SW_O: J205.3 U201.55
USB_D_N: D205.1 J201.2 U201.44
USB_D_P: D206.1 J201.3 U201.45
VB_A: C302.2 D301.1 U301.8
VB_B: C304.2 D302.1 U302.8
VB_C: C306.2 D303.1 U303.8
VBUS: D204.1 J201.1 R204.2
VBUS_SENSE: R203.2 R204.1 U201.50
VCAP: C212.2 U201.30
pads on no net: J201.4 J201.6 J201.7 J201.8 J201.9 J201.10 J201.11 J204.9 U201.26 U201.33 U201.37 U201.38 U201.39 U201.40 U201.52 U401.13

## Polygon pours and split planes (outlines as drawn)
no net on L2 (GND) (split plane): 65.629,31.983 65.757,31.958 65.879,31.916 65.996,31.859 66.104,31.787 66.201,31.701 66.287,31.604 66.359,31.496 66.416,31.379 66.458,31.257 66.483,31.129 66.491,31.012 66.49,31 66.49,-31 66.491,-31.012 66.483,-31.129 66.458,-31.257 66.416,-31.379 66.359,-31.496 66.287,-31.604 66.201,-31.701 66.104,-31.787 65.996,-31.859 65.879,-31.916 65.757,-31.958 65.629,-31.983 65.512,-31.991 65.5,-31.99 -65.5,-31.99 -65.512,-31.991 -65.629,-31.983 -65.757,-31.958 -65.879,-31.916 -65.996,-31.859 -66.104,-31.787 -66.201,-31.701 -66.287,-31.604 -66.359,-31.496 -66.416,-31.379 -66.458,-31.257 -66.483,-31.129 -66.491,-31.012 -66.49,-31 -66.49,31 -66.491,31.012 -66.483,31.129 -66.458,31.257 -66.416,31.379 -66.359,31.496 -66.287,31.604 -66.201,31.701 -66.104,31.787 -65.996,31.859 -65.879,31.916 -65.757,31.958 -65.629,31.983 -65.512,31.991 -65.5,31.99 65.5,31.99 65.512,31.991
no net on L3 (PWR) (split plane): 65.629,31.983 65.757,31.958 65.879,31.916 65.996,31.859 66.104,31.787 66.201,31.701 66.287,31.604 66.359,31.496 66.416,31.379 66.458,31.257 66.483,31.129 66.491,31.012 66.49,31 66.49,-31 66.491,-31.012 66.483,-31.129 66.458,-31.257 66.416,-31.379 66.359,-31.496 66.287,-31.604 66.201,-31.701 66.104,-31.787 65.996,-31.859 65.879,-31.916 65.757,-31.958 65.629,-31.983 65.512,-31.991 65.5,-31.99 -65.5,-31.99 -65.512,-31.991 -65.629,-31.983 -65.757,-31.958 -65.879,-31.916 -65.996,-31.859 -66.104,-31.787 -66.201,-31.701 -66.287,-31.604 -66.359,-31.496 -66.416,-31.379 -66.458,-31.257 -66.483,-31.129 -66.491,-31.012 -66.49,-31 -66.49,31 -66.491,31.012 -66.483,31.129 -66.458,31.257 -66.416,31.379 -66.359,31.496 -66.287,31.604 -66.201,31.701 -66.104,31.787 -65.996,31.859 -65.879,31.916 -65.757,31.958 -65.629,31.983 -65.512,31.991 -65.5,31.99 65.5,31.99 65.512,31.991

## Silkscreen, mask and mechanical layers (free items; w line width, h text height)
Mechanical 1:
  the board outline again, w0.1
